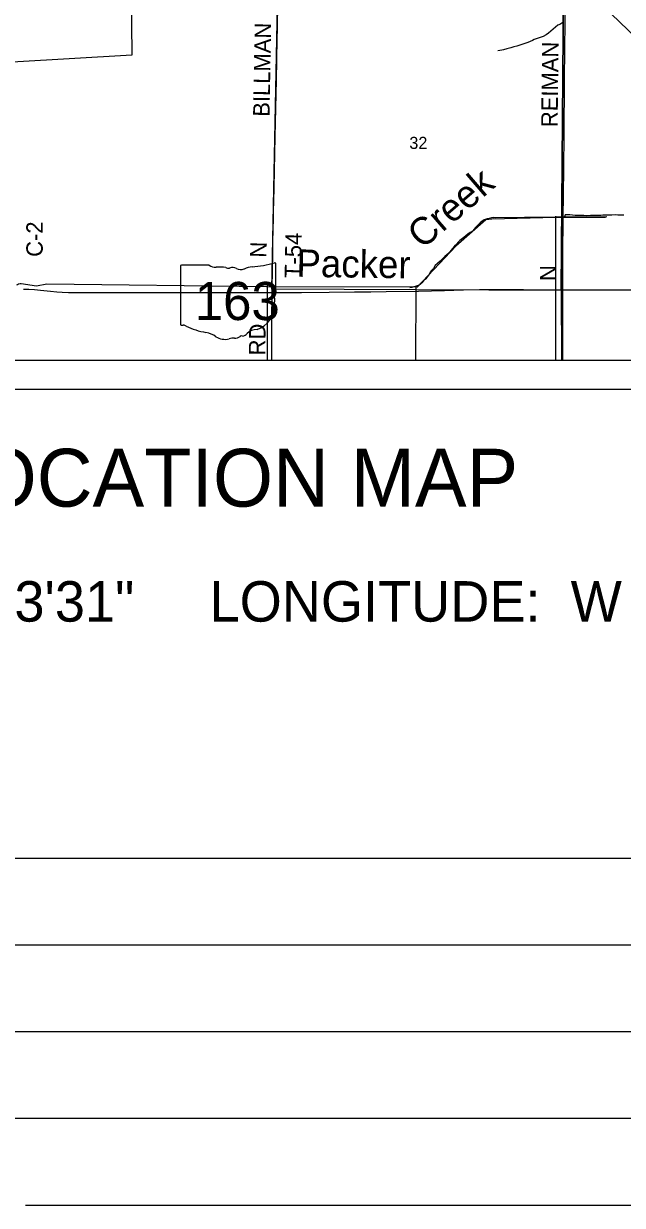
# Model space of a CAD drawing. Extents: x 0 to 34, y 0 to 22.
# Drawn here: x 4.739 to 6.808, y 11.177 to 15.265 of the extents above; entities that cross this region are included whole.
import ezdxf

# ---------------------------------------------------------------- set-up
doc = ezdxf.new("R2010")
doc.units = 0
for name, color, linetype in [('Default', 7, 'Continuous'), ('GM_X_County_Road_Text', 7, 'Continuous'), ('GM_X_Interstate_Route', 7, 'Continuous'), ('GM_X_Minor_River', 7, 'Continuous'), ('GM_X_Minor_River_Text', 7, 'Continuous'), ('GM_X_Rail_Line', 7, 'Continuous'), ('GM_X_Section', 7, 'Continuous'), ('GM_X_Section_Text', 7, 'Continuous'), ('GM_X_State_Location', 7, 'Continuous'), ('GM_X_State_Route', 7, 'Continuous'), ('GM_X_State_Shield', 7, 'Continuous'), ('GM_X_Township_Road', 7, 'Continuous'), ('GM_X_Township_Road_Text', 7, 'Continuous'), ('SH_Data', 7, 'Continuous'), ('SH_Text', 7, 'Continuous')]:
    doc.layers.add(name, color=color, linetype=linetype)

msp = doc.modelspace()

# ---------------------------------------------------------------- linework, layer by layer
at = {"layer": 'Default'}
msp.add_lwpolyline([(6.5976, 14.1), (7.6078, 14.1), (7.6069, 14.3511), (6.5967, 14.3417)], close=True, dxfattribs=at)
at = {"layer": 'GM_X_Interstate_Route'}
msp.add_lwpolyline([(4.7033, 15.2872), (4.704, 15.2372), (4.7044, 15.1626), (4.7047, 15.0849), (4.7047, 15.0383), (4.7052, 14.9668), (4.7054, 14.8953), (4.7055, 14.7399), (4.705, 14.6903), (4.7046, 14.5938), (4.705, 14.4959), (4.7052, 14.4725), (4.7052, 14.4414), (4.7052, 14.3917), (4.705, 14.347), (4.7049, 14.3358), (4.7038, 14.2643), (4.7028, 14.1744), (4.7022, 14.1275), (4.7021, 14.1056), (4.7021, 14.1), (8.9, 14.1), (8.9, 17.3895)], dxfattribs=at)
at = {"layer": 'GM_X_Minor_River'}
for p, q in [((6.5774, 14.5981), (6.577, 14.1)), ((5.5799, 14.3578), (5.5797, 14.1)), ((6.0936, 14.3559), (6.0929, 14.1))]:
    msp.add_line(p, q, dxfattribs=at)
for points in [[(6.7224, 15.3608), (5.1099, 15.3744), (5.1125, 15.1557), (4.6992, 15.1313)], [(6.6022, 15.2679), (6.592, 15.2618), (6.5848, 15.2588), (6.5765, 15.2523), (6.5689, 15.2451), (6.5613, 15.239), (6.5526, 15.2318), (6.5442, 15.2257), (6.5344, 15.2204), (6.5268, 15.2182), (6.5135, 15.2132), (6.5037, 15.2091), (6.4968, 15.206), (6.4889, 15.2022), (6.4809, 15.1992), (6.4639, 15.1935), (6.457, 15.1912), (6.4498, 15.1894), (6.443, 15.1871), (6.4324, 15.1844), (6.4225, 15.1803), (6.4081, 15.1772), (6.3975, 15.1734), (6.3911, 15.1723), (6.3839, 15.1716), (6.377, 15.1708)], [(6.3696, 14.593), (6.3624, 14.5937), (6.356, 14.5925), (6.348, 14.5906), (6.3412, 14.5895), (6.3306, 14.5853), (6.3238, 14.5815), (6.3162, 14.5759), (6.3067, 14.5667), (6.3002, 14.5595), (6.2953, 14.5531), (6.2896, 14.5463), (6.2817, 14.5421), (6.2741, 14.5368), (6.2665, 14.5303), (6.2555, 14.5208), (6.2464, 14.514), (6.2396, 14.5076), (6.2346, 14.5007), (6.2278, 14.495), (6.2214, 14.4871), (6.2153, 14.4802), (6.2092, 14.4719), (6.2013, 14.4651), (6.1948, 14.459), (6.1869, 14.4522), (6.1778, 14.4434), (6.169, 14.4351), (6.1615, 14.4279), (6.1546, 14.4176), (6.147, 14.4089), (6.1429, 14.4024), (6.1395, 14.396), (6.1334, 14.3884), (6.1281, 14.382), (6.1209, 14.3744), (6.1152, 14.3679), (6.1087, 14.3626), (6.1023, 14.3592), (6.0958, 14.3565), (6.0871, 14.3539), (6.0803, 14.352), (6.0739, 14.3509)], [(6.754, 14.5961), (6.5773, 14.595), (6.3628, 14.5929)], [(6.8131, 14.6017), (6.801, 14.6021), (6.7923, 14.6025), (6.7847, 14.6029), (6.7714, 14.6025), (6.7604, 14.6021), (6.7536, 14.6021), (6.7476, 14.6014), (6.7407, 14.6014), (6.7331, 14.601), (6.7085, 14.601), (6.6983, 14.6007), (6.685, 14.5999), (6.6748, 14.6003), (6.6566, 14.6003), (6.6444, 14.6011), (6.6353, 14.6015), (6.6259, 14.6026), (6.6164, 14.6034), (6.6103, 14.6026), (6.6081, 14.5962), (6.5963, 14.5931)], [(6.7502, 14.5934), (6.577, 14.5935), (6.3567, 14.5887), (6.3366, 14.5853), (6.2324, 14.4947), (6.0989, 14.3527), (5.5777, 14.3546), (4.8184, 14.3627), (4.7828, 14.3566), (4.7301, 14.365), (4.7259, 14.3643), (4.7202, 14.3628), (4.7168, 14.3609), (4.7142, 14.3594)]]:
    msp.add_lwpolyline(points, dxfattribs=at)
at = {"layer": 'GM_X_Rail_Line'}
msp.add_lwpolyline([(4.6999, 17.2234), (5.1959, 16.7623), (5.6141, 16.3779), (6.1219, 15.9048), (6.7692, 15.2987), (7.1796, 14.9035), (7.6056, 14.5217)], dxfattribs=at)
at = {"layer": 'GM_X_Section'}
for points in [[(6.5967, 14.3417), (5.5962, 14.3464), (5.6172, 15.3858), (6.6049, 15.379)], [(7.6191, 15.3755), (7.6069, 14.3511), (6.5967, 14.3417), (6.6049, 15.379)]]:
    msp.add_lwpolyline(points, close=True, dxfattribs=at)
at = {"layer": 'GM_X_State_Route'}
msp.add_lwpolyline([(4.7383, 14.3461), (4.7569, 14.3457), (4.7755, 14.3447), (4.7972, 14.3428), (4.8312, 14.3388), (4.8528, 14.3366), (4.8715, 14.3353), (4.8933, 14.3344), (4.9244, 14.3341), (5.0177, 14.3344), (5.083, 14.3341), (5.1358, 14.3343), (5.338, 14.3343), (5.4437, 14.3344), (5.4903, 14.3344), (5.5973, 14.3344), (5.6272, 14.3344), (5.6987, 14.3344), (5.7951, 14.3353), (5.8822, 14.3365), (5.9381, 14.3368), (5.991, 14.3377), (6.103, 14.3391), (6.1931, 14.3414), (6.2584, 14.3433), (6.3143, 14.3446), (6.3548, 14.3453), (6.4263, 14.3449), (6.4667, 14.3446), (6.5475, 14.3438), (6.6021, 14.3435), (6.6732, 14.3435), (6.8535, 14.3441)], dxfattribs=at)
at = {"layer": 'GM_X_State_Shield'}
for p, q in [((5.61, 14.3288), (5.61, 14.4335)), ((5.2804, 14.4251), (5.2804, 14.225)), ((5.3801, 14.4285), (5.2836, 14.4285)), ((5.6099, 14.3288), (5.61, 14.3288))]:
    msp.add_line(p, q, dxfattribs=at)
for centre, major_axis, start_param, end_param in [((5.4925, 14.7014), (0.3495, 0), 4.814394, 5.042369), ((5.6063, 14.4339), (0.00367, 0), 6.141152, 7.989035), ((5.2841, 14.4255), (0.00382, 0), 1.712693, 3.28349), ((5.4031, 14.4518), (0.037, 0), 4.042523, 4.731795), ((5.4154, 14.3162), (0.133, 0), 1.404758, 1.657858), ((5.4456, 14.4266), (0.0107, 0), 3.836095, 5.185415), ((5.4613, 14.4034), (0.0222, 0), 0.950623, 2.079405), ((5.4899, 14.4352), (0.0267, 0), 4.081561, 5.145723), ((5.5371, 14.3674), (0.0703, 0), 1.699011, 2.107814), ((5.6091, 14.3211), (0.00568, 0), 1.883978, 3.671073), ((5.573, 14.3079), (0.0341, 0), 5.934695, 6.695948), ((5.606, 14.3284), (0.00393, 0), 5.05454, 6.418171), ((5.5121, 14.2717), (0.0874, 0), 5.101752, 6.440018), ((5.6231, 14.285), (0.0248, 0), 2.387724, 3.262537), ((5.2842, 14.2245), (0.00385, 0), 3.00124, 4.508301), ((5.2848, 14.245), (0.0294, 0), 4.665946, 4.897461), ((5.2908, 14.2134), (0.0106, 0), 0.519207, 1.627899), ((5.4246, 14.3932), (0.2524, 0), 4.195997, 4.488961), ((5.3494, 14.1351), (0.079, 0), 0.823519, 1.323587), ((5.4883, 14.2056), (0.0282, 0), 4.937069, 5.64225), ((5.549, 14.1688), (0.0479, 0), 1.647645, 2.488434), ((5.4348, 14.2124), (0.0501, 0), 4.026481, 4.996735), ((5.4637, 14.1433), (0.0412, 0), 1.495662, 1.94098), ((5.4674, 14.1975), (0.0267, 0), 4.691044, 5.507374), ((5.4915, 14.1781), (0.00752, 0), 1.147584, 2.315152)]:
    msp.add_ellipse(centre, major_axis=major_axis, ratio=0.8, start_param=start_param, end_param=end_param, dxfattribs=at)
at = {"layer": 'GM_X_Township_Road'}
for points in [[(5.5973, 14.3344), (5.5974, 14.3452), (5.5987, 14.416), (5.5997, 14.4623), (5.6003, 14.5029), (5.6015, 14.558), (5.602, 14.5835), (5.6025, 14.6198), (5.6033, 14.6473), (5.6055, 14.7541), (5.6068, 14.8166), (5.6081, 14.8725), (5.6112, 15.022), (5.612, 15.0687), (5.6149, 15.2113), (5.6156, 15.2486), (5.6172, 15.3358), (5.6175, 15.3538), (5.6182, 15.3697), (5.6188, 15.3829), (5.6188, 15.3881)], [(6.604, 14.6478), (6.6041, 14.666), (6.6064, 14.8743), (6.6075, 15.0732), (6.61, 15.2721), (6.6106, 15.3312), (6.6117, 15.3813)], [(6.6034, 14.5591), (6.6039, 14.6194), (6.604, 14.6478)], [(6.6021, 14.3435), (6.602, 14.4049), (6.6025, 14.4547), (6.6027, 14.5044), (6.6033, 14.5541), (6.6034, 14.5591)], [(5.5958, 14.1), (5.5959, 14.1274), (5.5966, 14.2322), (5.5968, 14.2695), (5.597, 14.3015), (5.5973, 14.3333), (5.5973, 14.3344)], [(6.6023, 14.1), (6.6022, 14.1103), (6.602, 14.2196), (6.6017, 14.2752), (6.6018, 14.3189), (6.602, 14.3377), (6.6021, 14.3435)]]:
    msp.add_lwpolyline(points, dxfattribs=at)
at = {"layer": 'SH_Data'}
for p, q in [((2.1, 14.1), (8.9, 14.1)), ((2, 14), (9, 14)), ((7.7, 12.3767), (4.4937, 12.3767)), ((7.7, 12.0767), (3.9895, 12.0767)), ((7.7, 11.7767), (3.6192, 11.7767)), ((7.7, 11.4767), (3.3288, 11.4767)), ((7.7, 11.1767), (4.7452, 11.1767))]:
    msp.add_line(p, q, dxfattribs=at)

# ---------------------------------------------------------------- texts
at = {"layer": 'GM_X_County_Road_Text'}
msp.add_text('C-2', height=0.05682, rotation=89.9458, dxfattribs=at).set_placement((4.8045, 14.4578))
at = {"layer": 'GM_X_Minor_River_Text'}
for s, rotation, p in [('Creek', 40.6223, (6.1165, 14.4816)), ('Packer', 359.2001, (5.681, 14.3889))]:
    msp.add_text(s, height=0.09476, rotation=rotation, dxfattribs=at).set_placement(p)
at = {"layer": 'GM_X_Section_Text'}
msp.add_text('32', height=0.04186, rotation=0, dxfattribs=at).set_placement((6.0717, 14.8311))
at = {"layer": 'GM_X_State_Location'}
for s, p in [('s', (5.4415, 14.3117)), ('r', (5.4414, 14.3117))]:
    msp.add_text(s, height=0.000189, dxfattribs=at).set_placement(p)
msp.add_text('163', height=0.000189, rotation=0, dxfattribs=at).set_placement((5.3746, 14.298))
at = {"layer": 'GM_X_State_Shield'}
msp.add_text('163', height=0.13184, dxfattribs=at).set_placement((5.3298, 14.2391))
at = {"layer": 'GM_X_Township_Road_Text'}
for s, height, rotation, p in [('BILLMAN', 0.05682, 88.9712, (5.5883, 14.9421)), ('REIMAN', 0.05682, 89.3234, (6.5841, 14.9062)), ('T-54', 0.05682, 88.9519, (5.6974, 14.3845)), ('N', 0.0568, 88.0919, (5.5775, 14.4542)), ('N', 0.0568, 90, (6.58, 14.3743)), ('RD', 0.05682, 89.5105, (5.5739, 14.1167))]:
    msp.add_text(s, height=height, rotation=rotation, dxfattribs=at).set_placement(p)
at = {"layer": 'SH_Text'}
for s, height, p in [('LOCATION MAP', 0.2, (4.4269, 13.5938)), ('LATITUDE:  N 41°33\'31"     LONGITUDE:  W 83°24\'01"', 0.14, (3.071, 13.1959))]:
    msp.add_text(s, height=height, dxfattribs=at).set_placement(p)

doc.saveas('drawing.dxf')
